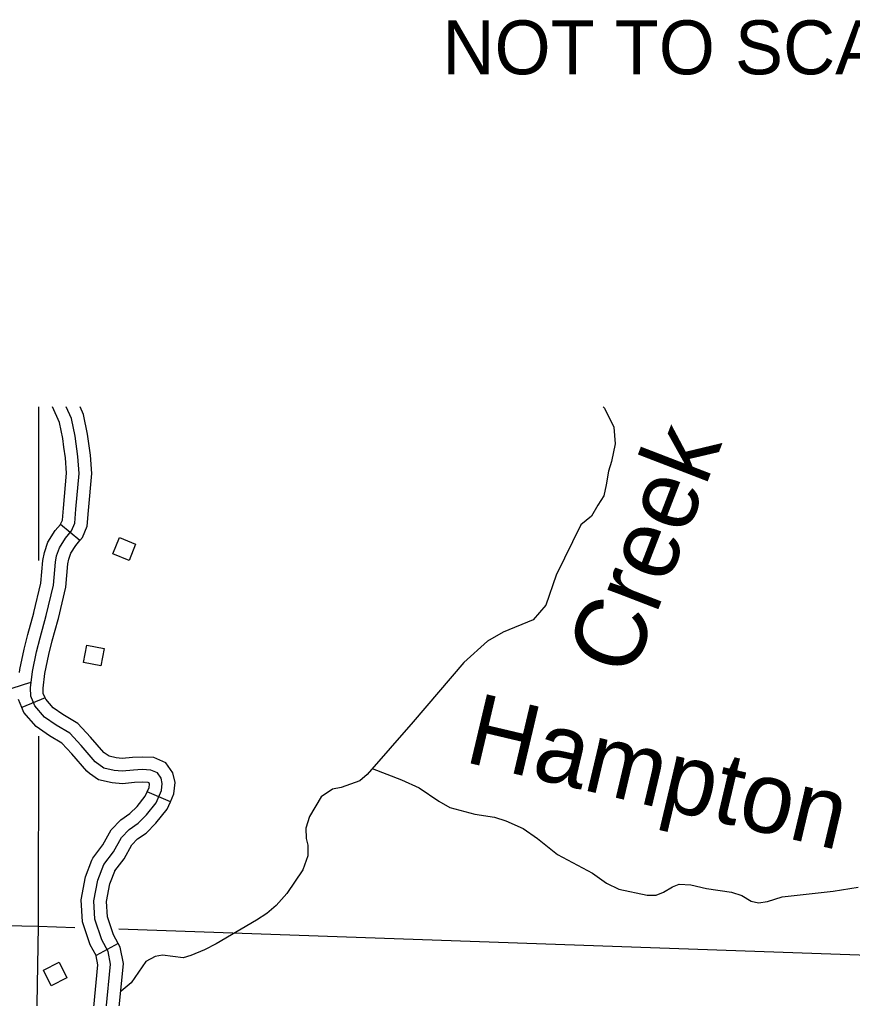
# Model space of a CAD drawing. Extents: x 1370130 to 1380143, y 377636 to 380256.
# Drawn here: x 1378335.4 to 1378543.5, y 378685.1 to 378929.7 of the extents above; entities that cross this region are included whole.
import ezdxf

# ---------------------------------------------------------------- set-up
doc = ezdxf.new("R2010")
doc.units = 0
for name, color, linetype in [('Level 35', 7, 'Continuous'), ('Level 45', 7, 'Continuous'), ('Level 5', 7, 'Continuous'), ('Level 56', 7, 'Continuous'), ('R_Draft', 7, 'Continuous')]:
    doc.layers.add(name, color=color, linetype=linetype)

msp = doc.modelspace()

# ---------------------------------------------------------------- linework, layer by layer
at = {"layer": 'Level 35'}
for points in [[(1378481.24, 378832.91), (1378481.54, 378832.56)], [(1378481.54, 378832.56), (1378483.89, 378827.85), (1378484.22, 378823.64), (1378483.28, 378819.25), (1378482.54, 378816.81), (1378481.93, 378813.43), (1378481.4, 378810.65)], [(1378481.4, 378810.65), (1378479.9, 378808.36), (1378478.27, 378805.57), (1378475.66, 378803.42), (1378469.49, 378790.88), (1378466.86, 378783.34), (1378463.68, 378779.65), (1378456.2, 378776.57), (1378452.34, 378774.37), (1378446.37, 378769.03), (1378433.73, 378754.15), (1378422.21, 378741.04), (1378420.38, 378739.46), (1378415.74, 378737.74), (1378413.58, 378737.33), (1378410.75, 378735.42), (1378407.83, 378730.52), (1378406.88, 378727.58), (1378407.02, 378725.02), (1378407.37, 378723.36), (1378407.38, 378720.71), (1378406.12, 378717.17), (1378402.14, 378711.31), (1378399.52, 378708.32), (1378397.16, 378706.3), (1378394.58, 378704.65), (1378384.52, 378698.7), (1378381.59, 378697.2), (1378378.21, 378695.78), (1378376.26, 378695.21), (1378371.11, 378695.9), (1378369.28, 378695.54), (1378366.94, 378694.28), (1378363.23, 378688.94), (1378360.79, 378686.87)], [(1378423.5, 378742.51), (1378430.82, 378739.72), (1378435.25, 378737.66), (1378440.11, 378734.34), (1378442.85, 378732.8), (1378449.11, 378731.13), (1378454.05, 378730.34), (1378456.85, 378729.43), (1378461.19, 378727.57), (1378464.76, 378725.05), (1378469.77, 378721.07), (1378478.58, 378716.34), (1378482.02, 378713.9), (1378485.09, 378712.33), (1378492.19, 378710.9), (1378494.41, 378710.85), (1378496.32, 378711.59), (1378498.49, 378712.97), (1378500.19, 378713.58), (1378503.08, 378713.43), (1378507.02, 378712.56), (1378513.3, 378711.61), (1378515.84, 378710.82), (1378518.2, 378709.35), (1378519.98, 378708.95), (1378522.23, 378709.28), (1378525.92, 378710.47), (1378538.7, 378711.89), (1378544.91, 378712.83)]]:
    msp.add_lwpolyline(points, dxfattribs=at)
at = {"layer": 'Level 45'}
for p, q in [((1378350.42, 378799.49), (1378345.58, 378803.52)), ((1378341.77, 378760.18), (1378335.95, 378757.76)), ((1378373.07, 378734.23), (1378367.29, 378736.73)), ((1378360.01, 378698.8), (1378354.49, 378695.76))]:
    msp.add_line(p, q, dxfattribs=at)
for points in [[(1378357.03, 378682.45), (1378358.14, 378693.64), (1378357.53, 378696.77), (1378355.92, 378699.69), (1378354.21, 378704.84), (1378353.91, 378709.47), (1378354.91, 378714.62), (1378356.43, 378718.55), (1378358.84, 378721.67), (1378360.86, 378725.3), (1378362.77, 378727.32), (1378364.99, 378728.83), (1378367.11, 378730.95), (1378369.53, 378733.98), (1378370.84, 378737), (1378371.04, 378738.82), (1378370.74, 378740.13), (1378369.83, 378741.44), (1378368.22, 378742.14), (1378366, 378742.24), (1378363.88, 378742.14), (1378361.06, 378741.84), (1378359.05, 378742.04), (1378356.43, 378742.65), (1378354.31, 378744.16), (1378350.78, 378748.29), (1378347.96, 378751.32), (1378344.53, 378753.34), (1378341.61, 378755.35), (1378339.19, 378758.18), (1378338.19, 378760.59), (1378338.09, 378762.71), (1378338.59, 378766.75), (1378339.6, 378771.69), (1378340.5, 378775.22), (1378342.02, 378780.76), (1378343.83, 378788.32), (1378344.33, 378794.07), (1378344.64, 378795.68), (1378345.34, 378797.7), (1378346.85, 378800.12), (1378348.36, 378801.94), (1378349.17, 378803.87), (1378349.47, 378807.3), (1378350.28, 378816.27), (1378349.98, 378820.51), (1378349.27, 378825.55), (1378348.36, 378829.99), (1378347.06, 378832.91)], [(1378346.47, 378822.86), (1378346.16, 378825.02), (1378345.35, 378829.02), (1378343.61, 378832.91)], [(1378352.7, 378823.74), (1378352.38, 378826.08), (1378351.38, 378830.96), (1378350.51, 378832.91)], [(1378345.58, 378803.52), (1378345.64, 378803.59), (1378346.07, 378804.63), (1378346.33, 378807.58), (1378347.12, 378816.3), (1378346.84, 378820.18), (1378346.47, 378822.86)], [(1378350.42, 378799.49), (1378351.09, 378800.29), (1378352.26, 378803.11), (1378352.61, 378807.02), (1378353.44, 378816.24), (1378353.11, 378820.84), (1378352.7, 378823.74)], [(1378338.92, 378781.4), (1378338.96, 378781.54), (1378340.71, 378788.83), (1378341.21, 378794.5), (1378341.58, 378796.5), (1378342.48, 378799.07), (1378344.29, 378801.97), (1378345.58, 378803.52)], [(1378345, 378779.74), (1378345.07, 378779.98), (1378346.95, 378787.82), (1378347.46, 378793.64), (1378347.69, 378794.87), (1378348.2, 378796.33), (1378349.41, 378798.27), (1378350.42, 378799.49)], [(1378335.39, 378766.52), (1378335.48, 378767.26), (1378336.53, 378772.39), (1378337.46, 378776.02), (1378338.92, 378781.4)], [(1378341.77, 378760.18), (1378341.31, 378761.3), (1378341.24, 378762.59), (1378341.7, 378766.23), (1378342.67, 378770.98), (1378343.55, 378774.41), (1378345, 378779.74)], [(1378271.14, 378685.18), (1378276.72, 378688.59), (1378281.78, 378693.03), (1378285.5, 378697.58), (1378289.11, 378700.47), (1378291.08, 378702.33), (1378293.14, 378704.81), (1378295.83, 378710.6), (1378303.06, 378727.03), (1378307.19, 378733.75), (1378312.66, 378741.09), (1378318.24, 378749.15), (1378322.37, 378754.93), (1378327.43, 378759.89), (1378329.91, 378761.55), (1378332.8, 378762.37), (1378336.62, 378763.61), (1378338.26, 378764.09)], [(1378335.95, 378757.76), (1378335.1, 378759.81)], [(1378356.55, 378746.43), (1378356.46, 378746.5), (1378353.13, 378750.39), (1378349.95, 378753.8), (1378346.23, 378755.99), (1378343.74, 378757.71), (1378341.91, 378759.85), (1378341.77, 378760.18)], [(1378352.88, 378741.31), (1378352.16, 378741.82), (1378348.43, 378746.2), (1378345.97, 378748.84), (1378342.84, 378750.68), (1378339.49, 378752.99), (1378336.48, 378756.5), (1378335.95, 378757.76)], [(1378373.07, 378734.23), (1378373.92, 378736.18), (1378374.23, 378739), (1378373.67, 378741.42), (1378371.91, 378743.96), (1378368.94, 378745.26), (1378366, 378745.4), (1378363.64, 378745.29), (1378361.05, 378745.01), (1378359.56, 378745.16), (1378357.75, 378745.58), (1378356.55, 378746.43)], [(1378367.29, 378736.73), (1378367.76, 378737.82), (1378367.85, 378738.63), (1378367.8, 378738.83), (1378367.75, 378738.91), (1378367.49, 378739.02), (1378366, 378739.09), (1378364.13, 378739), (1378361.07, 378738.67), (1378358.53, 378738.93), (1378355.11, 378739.72), (1378352.88, 378741.31)], [(1378353.45, 378719.58), (1378353.65, 378720.11), (1378356.21, 378723.41), (1378358.3, 378727.18), (1378360.72, 378729.73), (1378362.97, 378731.27), (1378364.76, 378733.05), (1378366.8, 378735.61), (1378367.29, 378736.73)], [(1378359.2, 378716.99), (1378361.48, 378719.94), (1378363.42, 378723.43), (1378364.83, 378724.91), (1378367.01, 378726.4), (1378369.46, 378728.85), (1378372.25, 378732.34), (1378373.07, 378734.23)], [(1378354.49, 378695.76), (1378353.02, 378698.42), (1378351.09, 378704.23), (1378350.74, 378709.68), (1378351.88, 378715.49), (1378353.45, 378719.58)], [(1378360.01, 378698.8), (1378358.82, 378700.96), (1378357.33, 378705.45), (1378357.08, 378709.27), (1378357.95, 378713.74), (1378359.33, 378717.32)], [(1378359.45, 378675.49), (1378359.38, 378677.13), (1378360.16, 378682.05), (1378361.32, 378693.79), (1378360.53, 378697.86), (1378360.01, 378698.8)], [(1378353.16, 378675.22), (1378353.06, 378677.49), (1378353.9, 378682.85), (1378354.96, 378693.5), (1378354.54, 378695.68), (1378354.49, 378695.76)]]:
    msp.add_lwpolyline(points, dxfattribs=at)
at = {"layer": 'Level 5'}
for points in [[(1378340.12, 378832.91), (1378340.1, 378794.5)], [(1378340.08, 378750.57), (1378340.06, 378703.15)], [(1378299.18, 378703.94), (1378340.06, 378703.15)], [(1378340.06, 378703.15), (1378337.41, 378551.4)], [(1378340.06, 378703.15), (1378349.16, 378702.83)], [(1378360.18, 378702.44), (1378559.43, 378695.42)]]:
    msp.add_lwpolyline(points, dxfattribs=at)
at = {"layer": 'Level 56'}
for points in [[(1378364.38, 378798.58), (1378362.74, 378794.53), (1378358.67, 378796.18), (1378360.32, 378800.23)], [(1378351.36, 378769.06), (1378352.19, 378773.35), (1378356.5, 378772.52), (1378355.67, 378768.22)], [(1378345.25, 378694.1), (1378347.21, 378690.19), (1378343.29, 378688.23), (1378341.33, 378692.14)]]:
    msp.add_lwpolyline(points, close=True, dxfattribs=at)

# ---------------------------------------------------------------- texts
at = {"layer": 'Level 35'}
for s, rotation, p in [('Creek', 68.9165, (1378488.24, 378764.82)), ('Hampton', 346.7087, (1378446.19, 378744.24))]:
    msp.add_text(s, height=17.741, rotation=rotation, dxfattribs=at).set_placement(p)
at = {"layer": 'R_Draft'}
msp.add_text('NOT TO SCALE', height=13.4776, dxfattribs=at).set_placement((1378441.05, 378916.02))

doc.saveas('drawing.dxf')
